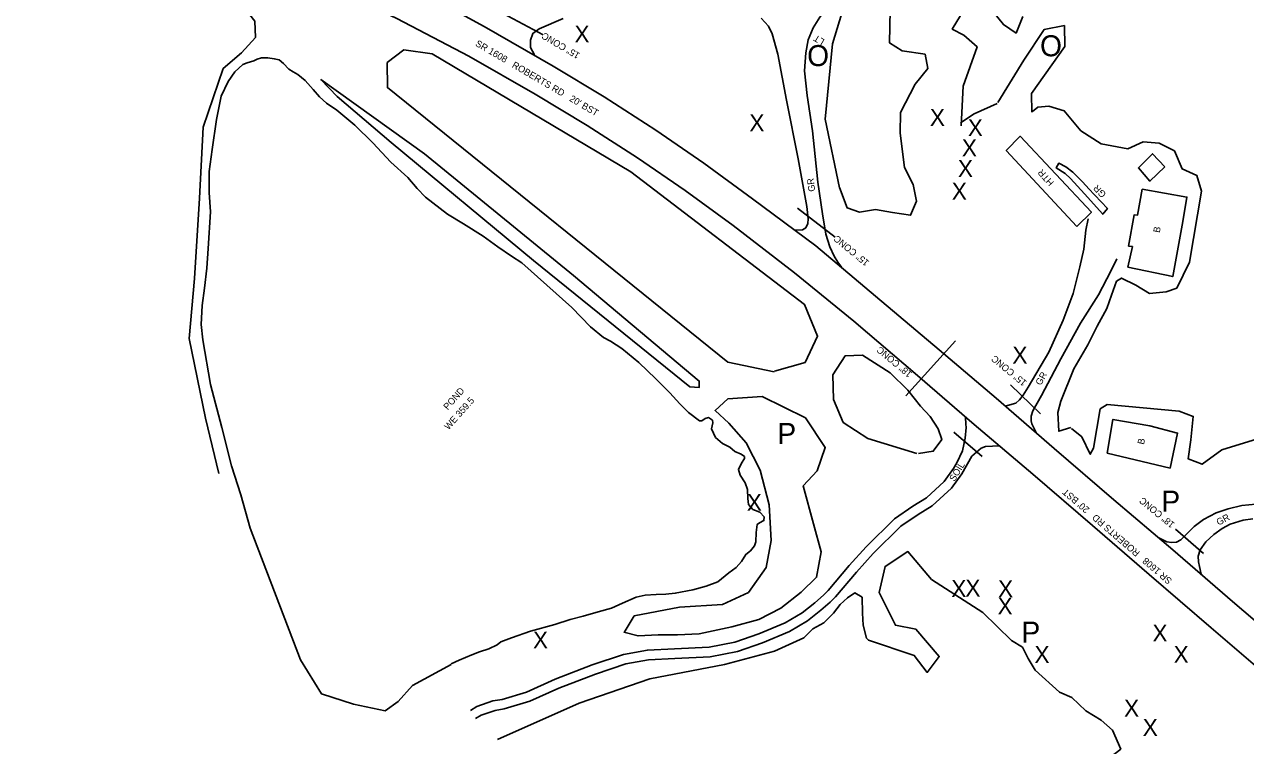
# Model space of a CAD drawing. Extents: x 2030130 to 2036320, y 723205 to 762423.
# Drawn here: x 2032654 to 2033381, y 734303 to 734732 of the extents above; entities that cross this region are included whole.
import ezdxf

# ---------------------------------------------------------------- set-up
doc = ezdxf.new("R2010")
doc.units = 0
for name, color, linetype in [('Draft_Station Cardinal Points', 7, 'Continuous'), ('Draft_Station Labels Major', 7, 'Continuous'), ('Draft_Station Tics Major', 7, 'Continuous'), ('Draft_Station Tics Minor', 7, 'Continuous'), ('Exist Terrain Model Ground Surface', 7, 'Continuous'), ('Old_Level_23', 7, 'Continuous'), ('Old_Level_26', 7, 'Continuous'), ('Old_Level_28', 7, 'Continuous'), ('Old_Level_29', 7, 'Continuous'), ('Prop Alignment Horizontal', 7, 'Continuous'), ('Prop Alignment Vertical', 7, 'Continuous'), ('Prop Horizontal Alignment Ramp', 7, 'Continuous')]:
    doc.layers.add(name, color=color, linetype=linetype)

msp = doc.modelspace()

# ---------------------------------------------------------------- linework, layer by layer
at = {"layer": 'Draft_Station Labels Major'}
for p, q in [((2033160.69, 734570.61), (2033198.44, 734538.71)), ((2033147.79, 734555.62), (2033185.63, 734523.46)), ((2033302.48, 734449.37), (2033337.5, 734419.76)), ((2033289.67, 734434.15), (2033323.47, 734405.07))]:
    msp.add_line(p, q, dxfattribs=at)
for points in [[(2033160.69, 734570.61), (2033125.06, 734600.58), (2033087.5, 734628.47), (2033058.5, 734649.74), (2033029.91, 734669.34), (2032999.27, 734689.05), (2032968.86, 734707.31), (2032927.77, 734730.95), (2032884.69, 734754.58), (2032841.26, 734774.32), (2032796.85, 734793.66), (2032752.41, 734812.16), (2032708.21, 734830.3), (2032662.1, 734849)], [(2032654.24, 734830.47), (2032700.61, 734811.41), (2032744.66, 734793.8), (2032789.48, 734775.31), (2032833.01, 734756.21), (2032875.85, 734735.66), (2032918.64, 734713.34), (2032958.2, 734690.79), (2032989.03, 734672.16), (2033019.09, 734652.88), (2033047.45, 734633.49), (2033075.91, 734612.59), (2033112.36, 734584.43), (2033147.79, 734555.62)], [(2033141.75, 734770.11), (2033135.39, 734751.94), (2033132.63, 734743.91), (2033130.36, 734739.95), (2033127.53, 734736.46), (2033123.48, 734730.22), (2033120.59, 734723.12), (2033119.23, 734715.39), (2033118.27, 734704.61), (2033119.97, 734689.84), (2033123.04, 734668.84), (2033126.37, 734638.42), (2033129.16, 734619.51), (2033131.03, 734607.4), (2033133.37, 734599.98), (2033136.07, 734594.47), (2033138.19, 734590.73), (2033140.28, 734587.78)], [(2032974.87, 734735.77), (2032960.44, 734729.68), (2032956.79, 734726.84), (2032955.41, 734722.83), (2032955.42, 734718.41), (2032957.79, 734714.2)], [(2033112.45, 734609.89), (2033117.23, 734610.1), (2033119.17, 734611.23), (2033120.42, 734613.77), (2033120.56, 734616.64), (2033119.68, 734623.92), (2033114.64, 734652.19), (2033107.56, 734687.17), (2033102.46, 734714.55), (2033099.19, 734726.65), (2033096.99, 734731.11), (2033092.68, 734735.89)], [(2033237.74, 734505.24), (2033244.06, 734507.02), (2033246.21, 734508.89), (2033248.45, 734511.74), (2033251.36, 734516.51), (2033263.7, 734537.36), (2033272.27, 734556.3), (2033278.16, 734572.23), (2033282.18, 734588), (2033284.57, 734598.53), (2033285.66, 734609.75), (2033287.09, 734616.65)], [(2033256.41, 734489.03), (2033253.68, 734494.74), (2033253.19, 734496.49), (2033253.28, 734499.18), (2033254.2, 734502.32), (2033259.41, 734511.52), (2033270.9, 734533.22), (2033282.56, 734554.47), (2033293.22, 734571.3), (2033300.56, 734585.39), (2033304.26, 734592.84)], [(2033198.44, 734538.71), (2033232.44, 734509.83), (2033266.9, 734479.95), (2033302.48, 734449.37)], [(2033289.67, 734434.15), (2033254.12, 734464.76), (2033219.27, 734494.2), (2033185.63, 734523.46)], [(2033208.98, 734471.44), (2033212.28, 734478.6), (2033214.02, 734486.21), (2033214.46, 734492.5), (2033214.3, 734494.36), (2033214.12, 734498.68)], [(2033234.34, 734481.48), (2033226.14, 734481.27), (2033223.4, 734480.16), (2033217.88, 734475.37), (2033211.92, 734464.98), (2033205.81, 734456.44), (2033194.4, 734445.95), (2033186.06, 734440.78), (2033175.65, 734433.7), (2033159.28, 734417.55), (2033149.32, 734406.53), (2033136.76, 734391.76), (2033133.71, 734388.55), (2033128.18, 734383.75), (2033120.22, 734377.46), (2033109.42, 734371.1), (2033093.31, 734364.4), (2033078.45, 734359.23), (2033062.3, 734356.15), (2033041.3, 734355), (2033025.55, 734354.31), (2033012.09, 734351.84), (2032994.06, 734345.8), (2032972.16, 734337.49), (2032954.93, 734329.71), (2032939.75, 734325.14), (2032934.27, 734324.24), (2032926, 734321.36), (2032922.69, 734319.32)], [(2033208.98, 734471.44), (2033207.06, 734468.1), (2033201.46, 734460.29), (2033190.89, 734450.57), (2033182.91, 734445.62), (2033171.97, 734438.18), (2033155.1, 734421.54), (2033144.98, 734410.34), (2033132.46, 734395.62), (2033129.71, 734392.72), (2033124.5, 734388.2), (2033116.95, 734382.24), (2033106.84, 734376.28), (2033091.25, 734369.8), (2033076.96, 734364.83), (2033061.6, 734361.9), (2033041.02, 734360.77), (2033024.9, 734360.06), (2033010.64, 734357.45), (2032992.12, 734351.24), (2032969.95, 734342.82), (2032952.9, 734335.13), (2032938.44, 734330.78), (2032932.84, 734329.86), (2032923.5, 734326.6), (2032919.66, 734324.23)], [(2033386.98, 734446.8), (2033378.64, 734446.1), (2033370.44, 734444.14), (2033363.28, 734441.77), (2033355.75, 734437.68), (2033350.13, 734433.52), (2033345.16, 734428.66), (2033342.36, 734425.63), (2033339.72, 734424.21), (2033336.94, 734424.04), (2033334, 734424.54), (2033328.79, 734427.12)], [(2033385.03, 734438.2), (2033379.36, 734437.39), (2033371.62, 734434.94), (2033366.83, 734432.46), (2033361.81, 734428.75), (2033357.24, 734424.55), (2033353.69, 734419.63), (2033352.58, 734415.86), (2033352.73, 734412.6), (2033353.47, 734409.71), (2033354.32, 734405.19)], [(2033650.79, 734146.66), (2033617.2, 734178), (2033582.2, 734209.27), (2033547.47, 734239.33), (2033513.42, 734268.75), (2033478.55, 734298.65), (2033443.75, 734328.41), (2033408.02, 734358.96), (2033372.98, 734389.04), (2033337.5, 734419.76)], [(2033323.47, 734405.07), (2033360.4, 734373.29), (2033395.11, 734343.65), (2033431.25, 734312.99), (2033465.65, 734283.39), (2033500.39, 734253.62), (2033534.59, 734223.99), (2033568.5, 734194.34), (2033602.82, 734163.7), (2033636.33, 734131.87), (2033659.89, 734108.31), (2033683.47, 734083.08), (2033706.23, 734056.78), (2033727.14, 734030.65), (2033748.01, 734002.9), (2033774.83, 733965.52)]]:
    msp.add_lwpolyline(points, dxfattribs=at)
at = {"layer": 'Draft_Station Tics Major'}
for points in [[(2033139.21, 734635.08), (2033130.61, 734675.8), (2033134.99, 734720.73), (2033146.05, 734757.37), (2033156.37, 734773.39), (2033165.13, 734789.56), (2033174.33, 734787.46), (2033169.52, 734750.58), (2033169.03, 734721.25), (2033176.47, 734716.56), (2033190.09, 734714.47), (2033191.82, 734706.04), (2033184.25, 734696.63), (2033175.39, 734679.79), (2033175.2, 734667.51), (2033177.85, 734647.19), (2033182.97, 734636.96), (2033185.06, 734627.03), (2033181.52, 734618.74), (2033170.75, 734620.3), (2033160.65, 734622.07), (2033150.99, 734620.59), (2033143.72, 734623.13), (2033139.14, 734635.2)], [(2032778.55, 734750.35), (2032791.28, 734734.22), (2032791.63, 734724.48), (2032783.3, 734715.28), (2032772.55, 734705.99), (2032760.51, 734671.18), (2032758.32, 734628.86), (2032755.35, 734581.14), (2032752.31, 734545.49), (2032762.07, 734498.05), (2032769.85, 734465.05)], [(2033211.61, 734671.95), (2033212.86, 734695.53), (2033221.03, 734718.9), (2033213.14, 734725.82), (2033206.28, 734729.44), (2033216.14, 734745.59)], [(2033230.78, 734739.49), (2033236.74, 734732.13), (2033244.29, 734727.1), (2033248.19, 734736.98)], [(2033253.53, 734680.09), (2033253.42, 734691.2), (2033273.23, 734719.14), (2033272.98, 734731.52), (2033260.96, 734729.2), (2033248.85, 734710.9), (2033233.36, 734685.79)], [(2033100.24, 734525.66), (2033072.78, 734531.31), (2032870.17, 734694.62), (2032870.12, 734709.49), (2032879.97, 734717.04), (2032896.76, 734714.72), (2033015.05, 734644.44), (2033118.42, 734565.69), (2033126.11, 734546.77), (2033118.69, 734531.08), (2033100.53, 734525.97)], [(2033050.23, 734516.72), (2032957.05, 734591.87), (2032872.5, 734662.06), (2032840.26, 734689.31), (2032830.62, 734699.41), (2032892.32, 734655.18), (2032980.89, 734582.79), (2033055.77, 734520.09), (2033055.77, 734516.27), (2033050.23, 734516.72)], [(2033233.05, 734685.27), (2033219.38, 734679.09), (2033211.13, 734673.6)], [(2033294.91, 734661.21), (2033282.76, 734668.99), (2033272.9, 734680.81), (2033263.79, 734683.58), (2033257.11, 734683.04), (2033254.07, 734680.44)], [(2033315.48, 734577.07), (2033323.65, 734572.23), (2033333.55, 734573.15), (2033339.89, 734575.35), (2033347.36, 734590.78), (2033354.6, 734632.95), (2033351.77, 734642.36), (2033343.02, 734646.33), (2033338.53, 734656.94), (2033329.43, 734661.49), (2033319.8, 734662.45), (2033310.71, 734658.28), (2033294.91, 734661.21)], [(2033276.86, 734492.47), (2033269.63, 734490.2), (2033269.1, 734501.39), (2033270.87, 734508.1), (2033278.52, 734527.32), (2033286.96, 734541.7), (2033292.59, 734552.69), (2033298.3, 734563.25), (2033301.01, 734571.09), (2033304.06, 734579.42), (2033307.03, 734581.36), (2033315.48, 734577.07)], [(2033185.14, 734477.03), (2033156.04, 734485.98), (2033141.38, 734495.51), (2033135.52, 734509.07), (2033135.23, 734523.81), (2033142.57, 734535.11), (2033152.92, 734535.48), (2033169.32, 734525.04), (2033179.75, 734514.75), (2033187.36, 734505.09), (2033193.19, 734498.96), (2033197.9, 734491.76), (2033200.02, 734485.31), (2033194.97, 734478.36), (2033186.12, 734476.94)], [(2033011.11, 734370.53), (2033017.03, 734380.43), (2033044.03, 734385.56), (2033069.63, 734387.27), (2033084.98, 734394.41), (2033095.54, 734409.18), (2033098.44, 734425.19), (2033097.25, 734446.42), (2033092.05, 734467.02), (2033083.6, 734483.36), (2033073.36, 734495), (2033065.16, 734502.63), (2033072.78, 734509.43), (2033093.09, 734510.89), (2033118.9, 734498.29), (2033130.76, 734480.55), (2033125.89, 734466.72), (2033117.62, 734457.71), (2033123.68, 734435.25), (2033128.19, 734418.46), (2033125.56, 734403.37), (2033116.37, 734394.63), (2033104.28, 734384.93), (2033091.29, 734378.3), (2033075.17, 734374), (2033055.64, 734369.7), (2033042.85, 734369.24), (2033031.39, 734369.19), (2033019.35, 734368.51), (2033010.79, 734370.82)], [(2033390.45, 734486.61), (2033366.63, 734479.26), (2033354.9, 734470.64), (2033346.69, 734473.82), (2033348.29, 734485.13), (2033349.63, 734499.11), (2033341.22, 734502.11), (2033298.54, 734506.15), (2033294.26, 734503.49), (2033290.26, 734480.14), (2033288.41, 734476.61), (2033283.46, 734486.92), (2033277.17, 734491.85)], [(2033156.54, 734365.98), (2033183.69, 734356.92), (2033191.37, 734346.83), (2033198.58, 734356.36), (2033184.65, 734372.5), (2033172.49, 734374.86), (2033162.77, 734394.38), (2033166.29, 734409.81), (2033179.93, 734418.65), (2033193.94, 734402.09), (2033224.4, 734382.38)], [(2033118.02, 734367.44), (2033123.34, 734372.64), (2033129.84, 734376.35), (2033135.61, 734381.98), (2033139.68, 734387.3), (2033143.9, 734391.08), (2033148.3, 734394.1), (2033152.74, 734391.49), (2033152.9, 734382.11), (2033153.19, 734374.91), (2033155.26, 734367.28), (2033156.54, 734365.98)], [(2033224.4, 734382.38), (2033241.54, 734365.74), (2033248.01, 734361.87), (2033251.52, 734355.09), (2033255.59, 734348.09), (2033270.03, 734334.98), (2033277.48, 734331.83), (2033285.69, 734323.91), (2033294.94, 734318.4), (2033301.71, 734312.44), (2033306.56, 734301.24), (2033300.67, 734296.55), (2033302.87, 734290.02), (2033310.45, 734290.08), (2033317.22, 734293.21), (2033323.69, 734293.7), (2033326.66, 734287.7), (2033328.31, 734281.76), (2033336.25, 734276.5), (2033345.6, 734273.46), (2033354.92, 734264.92), (2033359.69, 734261.12)], [(2032935.68, 734306.87), (2032984.22, 734328.56), (2033026.42, 734343.07), (2033070.68, 734351.56), (2033100.58, 734359.51), (2033118.02, 734367.44)]]:
    msp.add_lwpolyline(points, dxfattribs=at)
at = {"layer": 'Draft_Station Tics Minor'}
msp.add_line((2033178.68, 734511.36), (2033208.27, 734543.99), dxfattribs=at)
for points in [[(2032962.8, 734726.02), (2032939.02, 734738.62)], [(2033136.63, 734605.76), (2033114.29, 734622.95)], [(2033258.71, 734500.59), (2033240.88, 734517.76)], [(2033223.98, 734475.29), (2033207.23, 734489.63)], [(2033355.85, 734417.58), (2033339.15, 734431.93)]]:
    msp.add_lwpolyline(points, dxfattribs=at)
at = {"layer": 'Exist Terrain Model Ground Surface'}
for points in [[(2033280.3, 734612.06), (2033238.38, 734657.16), (2033246.72, 734665.74), (2033289.1, 734620.5)], [(2033332.76, 734647.45), (2033323.87, 734638.9), (2033317.03, 734646.84), (2033325.33, 734655.32)], [(2033319.32, 734634.24), (2033345.88, 734629.47), (2033343.44, 734614.93), (2033337.43, 734582.22), (2033310.82, 734587.88), (2033313.45, 734600.08), (2033311.14, 734600.37), (2033314.43, 734618.94), (2033316.46, 734618.76)], [(2033298.52, 734477.28), (2033301.83, 734497.29), (2033323.84, 734493.52), (2033340.37, 734489.11), (2033335.89, 734468.37)]]:
    msp.add_lwpolyline(points, close=True, dxfattribs=at)
for points in [[(2033284.89, 734631.41), (2033280.87, 734635.99), (2033276.63, 734640.5), (2033273.43, 734643.61), (2033268.16, 734646.9), (2033269.65, 734649.68), (2033273.83, 734647.44), (2033277.92, 734644.28), (2033283.73, 734638.5), (2033287.8, 734634.13)], [(2033287.35, 734634.6), (2033298.59, 734622.7), (2033295.83, 734619.32), (2033284.89, 734631.41)]]:
    msp.add_lwpolyline(points, dxfattribs=at)
at = {"layer": 'Prop Alignment Horizontal'}
for points in [[(2032788.49, 734432.67), (2032782.94, 734452.37), (2032777.49, 734469.73), (2032771.71, 734492.41), (2032764.99, 734518.07), (2032760.44, 734544.61), (2032759.43, 734553.83), (2032760, 734565.01), (2032761.46, 734575.43), (2032762.8, 734587.18), (2032763.53, 734598.91), (2032765, 734620.66), (2032764.16, 734632.15), (2032764.25, 734644.77), (2032765.95, 734657.73), (2032768.53, 734675.74), (2032771.29, 734689.59), (2032775.55, 734698.27), (2032779.46, 734704.05), (2032784.26, 734708.46), (2032786.85, 734709.41), (2032790.68, 734710.49), (2032792.72, 734711.6), (2032795.37, 734712.43), (2032799.06, 734712.35), (2032802.92, 734711.82), (2032805.81, 734711.07), (2032808.48, 734708.88), (2032811.62, 734705.55), (2032814.05, 734703.93), (2032816.82, 734702.42), (2032821.19, 734698.82), (2032826.04, 734693.48), (2032829.86, 734689.05), (2032833.92, 734685.45), (2032840.2, 734681.19), (2032850.85, 734672.34), (2032861.48, 734661.69), (2032872.19, 734650.32), (2032882.43, 734641.09), (2032887.97, 734634.64), (2032892.88, 734629.48), (2032905.98, 734619.41), (2032915.42, 734613.63), (2032927.09, 734606.19), (2032935.91, 734599.98), (2032944.12, 734594.46), (2032950.09, 734590.5), (2032979.98, 734563.75), (2032991.06, 734552.26), (2032998.87, 734546.05), (2033003.04, 734543.83), (2033009.71, 734539.56), (2033019.77, 734531.08), (2033029.9, 734521.48), (2033038.31, 734513.19), (2033044.28, 734506.52), (2033049.31, 734501.43), (2033055.96, 734496.36), (2033057.36, 734496.35), (2033059.17, 734497.73), (2033061.16, 734498.35), (2033063.62, 734496.82), (2033063.77, 734495.27), (2033063.13, 734491.75), (2033065.33, 734486.58), (2033069.58, 734482.93), (2033073.95, 734480.74), (2033076.85, 734478.28), (2033080.59, 734476.68), (2033082.75, 734475.14), (2033082.64, 734474.07), (2033080.88, 734471.17), (2033079, 734467.51), (2033080.13, 734464.17), (2033083.07, 734459.49), (2033084.43, 734455.58), (2033084.59, 734450.31), (2033085.03, 734446.67), (2033087.69, 734443.78), (2033091.72, 734442.09), (2033094.34, 734439.41), (2033094.18, 734437.15), (2033091.58, 734435.81), (2033090.3, 734434.88), (2033089.65, 734429.95), (2033089.36, 734424.51), (2033088.57, 734422.14), (2033086.29, 734419.19), (2033083.54, 734416.99), (2033080.98, 734412.72), (2033077.75, 734409.25), (2033073.39, 734406.02), (2033066.82, 734400.72), (2033059.93, 734398.12), (2033051.84, 734395.88), (2033041.43, 734393.92), (2033035.87, 734393.44), (2033030.15, 734393.12), (2033023.61, 734392.73), (2033018.14, 734391.52)], [(2032788.49, 734432.67), (2032818.56, 734354.33), (2032830.94, 734334.05), (2032850.03, 734327.93), (2032868.88, 734323.91), (2032876.67, 734329.61), (2032885.04, 734339.03), (2032908.2, 734351.45)], [(2033018.14, 734391.52), (2033010, 734388.09), (2033003.56, 734384.96), (2032995.69, 734382.76), (2032986.63, 734380.3), (2032979, 734378.22), (2032969.83, 734375.39), (2032955.38, 734371.31), (2032944.09, 734367.39), (2032937.78, 734365.03), (2032935.47, 734363.3), (2032930.62, 734360.81), (2032925.07, 734359.03), (2032920.44, 734357.27), (2032913, 734354.14), (2032908.05, 734351.98)]]:
    msp.add_lwpolyline(points, dxfattribs=at)

# ---------------------------------------------------------------- texts
at = {"layer": 'Draft_Station Cardinal Points'}
for p in [(2033258.52, 734713.26), (2033119.96, 734707.42)]:
    msp.add_text('O', height=12.5, dxfattribs=at).set_placement(p)
at = {"layer": 'Draft_Station Tics Major'}
for p in [(2032981.53, 734721.49), (2033192.99, 734671.86), (2033085.57, 734668.66), (2033215.54, 734665.77), (2033212.02, 734653.79), (2033209.65, 734641.49), (2033206.03, 734628), (2033242.07, 734530.53), (2033084.08, 734443.02), (2033205.71, 734391.71), (2033214.1, 734391.96), (2033233.55, 734391.56), (2033233.25, 734381.32), (2033325.41, 734365.2), (2032956.83, 734361.13), (2033255.22, 734352.48), (2033338.01, 734352.52), (2033308.51, 734320.55), (2033319.62, 734309.09)]:
    msp.add_text('X', height=10, dxfattribs=at).set_placement(p)
at = {"layer": 'Old_Level_23'}
for s, rotation, p in [("SR 1608   ROBERTS RD   20' BST", 329.63618, (2032922.16, 734719.72)), ('GR', 97.78207, (2033124.8, 734633.03)), ('GR', 60.40328, (2033258.97, 734517.17)), ('SOIL', 58.47214, (2033207.63, 734460.05)), ("SR 1608   ROBERTS RD   20' BST", 139.26703, (2033337.39, 734401.88)), ('GR', 28.13611, (2033364.73, 734434.07))]:
    msp.add_text(s, height=4, rotation=rotation, dxfattribs=at).set_placement(p)
at = {"layer": 'Old_Level_26'}
for s, rotation, p in [('15" CONC', 149.31727, (2032985.15, 734714.84)), ('15" CONC', 140.50502, (2033157.2, 734591.14)), ('18" CONC', 140.22477, (2033182.73, 734524.91)), ('15" CONC', 140.50502, (2033250.97, 734519.75)), ('18" CONC', 140.50502, (2033339.01, 734435.38))]:
    msp.add_text(s, height=4, rotation=rotation, dxfattribs=at).set_placement(p)
at = {"layer": 'Old_Level_28'}
for s, rotation, p in [('HTR', 131.83638, (2033267.06, 734638.31)), ('GR', 133.78244, (2033298.19, 734631.45)), ('B', 79.27039, (2033329.71, 734608.07)), ('B', 77.93733, (2033320.3, 734482.09))]:
    msp.add_text(s, height=4, rotation=rotation, dxfattribs=at).set_placement(p)
at = {"layer": 'Old_Level_29'}
msp.add_text('LT', height=4, rotation=148.66706, dxfattribs=at).set_placement((2033130.67, 734723))
at = {"layer": 'Prop Alignment Vertical'}
for s, rotation, p in [('POND', 48.21959, (2032906.07, 734502.59)), ('WE 359.5', 48.16465, (2032906.58, 734490.77))]:
    msp.add_text(s, height=4, rotation=rotation, dxfattribs=at).set_placement(p)
at = {"layer": 'Prop Horizontal Alignment Ramp'}
for p in [(2033102.24, 734482.64), (2033330.72, 734442.41), (2033247.47, 734364.52)]:
    msp.add_text('P', height=12.5, dxfattribs=at).set_placement(p)

doc.saveas('drawing.dxf')
